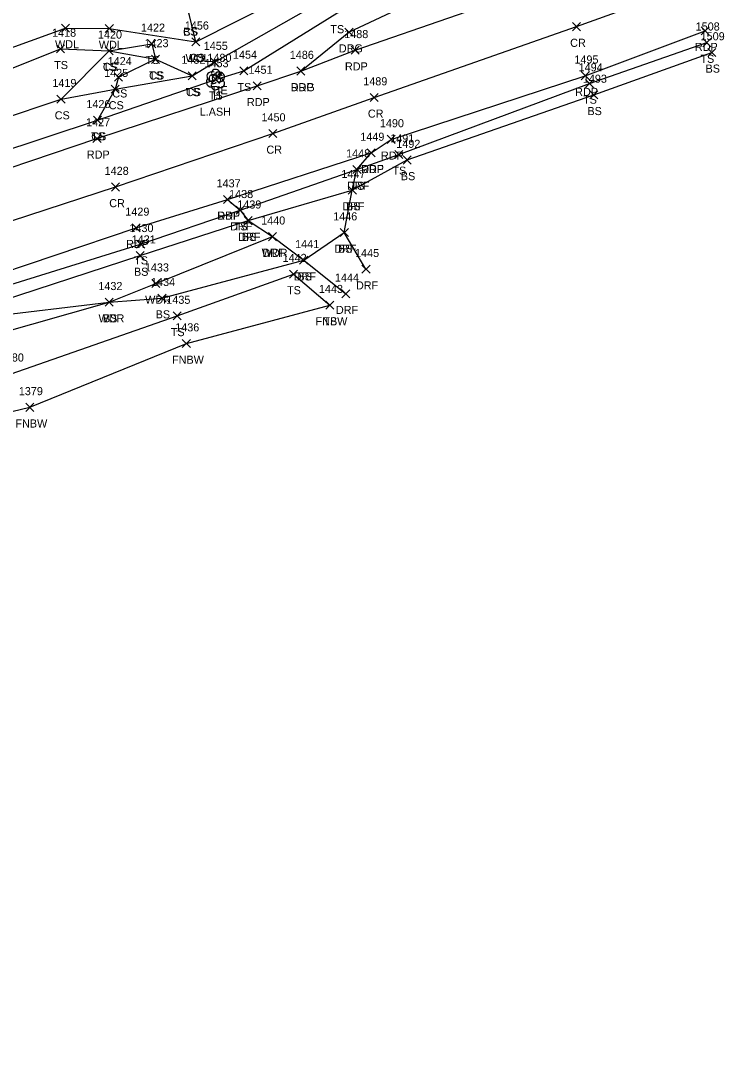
# Model space of a CAD drawing. Extents: x 1443064 to 1445163, y 544063 to 544655.
# Drawn here: x 1443666.1 to 1443840.1, y 544086.5 to 544343.6 of the extents above; entities that cross this region are included whole.
import ezdxf

# ---------------------------------------------------------------- set-up
doc = ezdxf.new("R2010")
doc.units = 0
for name, color, linetype in [('C_A', 7, 'Continuous'), ('C_I', 7, 'Continuous'), ('CBP', 7, 'Continuous'), ('L_A', 7, 'Continuous'), ('L_C', 7, 'Continuous'), ('L_I', 7, 'Continuous'), ('L_TIC', 7, 'Continuous'), ('LAWA', 7, 'Continuous'), ('LELB', 7, 'Continuous'), ('LFNC', 7, 'Continuous'), ('LTD', 7, 'Continuous'), ('P_A', 7, 'Continuous'), ('P_I', 7, 'Continuous'), ('P_TIC', 7, 'Continuous'), ('PET', 7, 'Continuous'), ('PRC', 7, 'Continuous'), ('R_A', 7, 'Continuous'), ('R_I', 7, 'Continuous'), ('R_TIC', 7, 'Continuous'), ('RDF', 7, 'Continuous'), ('RDG', 7, 'Continuous')]:
    doc.layers.add(name, color=color, linetype=linetype)

msp = doc.modelspace()

# ---------------------------------------------------------------- linework, layer by layer
at = {"layer": 'CBP'}
for radius in [0.625, 0.0833]:
    msp.add_circle((1443715.06, 544330.48), radius, dxfattribs=at)
at = {"layer": 'L_TIC'}
for points in [[(1443676.18, 544340.83), (1443678.18, 544342.83)], [(1443678.18, 544340.83), (1443676.18, 544342.83)], [(1443687.03, 544340.71), (1443689.03, 544342.71)], [(1443689.03, 544340.71), (1443687.03, 544342.71)], [(1443674.99, 544335.7), (1443676.99, 544337.7)], [(1443676.99, 544335.7), (1443674.99, 544337.7)], [(1443687, 544335.24), (1443689, 544337.24)], [(1443689, 544335.24), (1443687, 544337.24)], [(1443687, 544335.24), (1443689, 544337.24)], [(1443689, 544335.24), (1443687, 544337.24)], [(1443697.55, 544336.96), (1443699.55, 544338.96)], [(1443699.55, 544336.96), (1443697.55, 544338.96)], [(1443708.45, 544337.47), (1443710.45, 544339.47)], [(1443710.45, 544337.47), (1443708.45, 544339.47)], [(1443708.45, 544337.47), (1443710.45, 544339.47)], [(1443710.45, 544337.47), (1443708.45, 544339.47)], [(1443834.8, 544337.24), (1443836.8, 544339.24)], [(1443836.8, 544337.24), (1443834.8, 544339.24)], [(1443698.43, 544333.12), (1443700.43, 544335.12)], [(1443700.43, 544333.12), (1443698.43, 544335.12)], [(1443698.43, 544333.12), (1443700.43, 544335.12)], [(1443700.43, 544333.12), (1443698.43, 544335.12)], [(1443713.07, 544332.45), (1443715.07, 544334.45)], [(1443715.07, 544332.45), (1443713.07, 544334.45)], [(1443836.04, 544334.82), (1443838.04, 544336.82)], [(1443838.04, 544334.82), (1443836.04, 544336.82)], [(1443720.31, 544330.26), (1443722.31, 544332.26)], [(1443722.31, 544330.26), (1443720.31, 544332.26)], [(1443689.33, 544328.68), (1443691.33, 544330.68)], [(1443691.33, 544328.68), (1443689.33, 544330.68)], [(1443707.55, 544329.01), (1443709.55, 544331.01)], [(1443709.55, 544329.01), (1443707.55, 544331.01)], [(1443707.55, 544329.01), (1443709.55, 544331.01)], [(1443709.55, 544329.01), (1443707.55, 544331.01)], [(1443713.26, 544328.16), (1443715.26, 544330.16)], [(1443715.26, 544328.16), (1443713.26, 544330.16)], [(1443688.45, 544325.75), (1443690.45, 544327.75)], [(1443690.45, 544325.75), (1443688.45, 544327.75)], [(1443688.45, 544325.75), (1443690.45, 544327.75)], [(1443690.45, 544325.75), (1443688.45, 544327.75)], [(1443805.78, 544327.14), (1443807.78, 544329.14)], [(1443807.78, 544327.14), (1443805.78, 544329.14)], [(1443675.09, 544323.26), (1443677.09, 544325.26)], [(1443677.09, 544323.26), (1443675.09, 544325.26)], [(1443675.09, 544323.26), (1443677.09, 544325.26)], [(1443677.09, 544323.26), (1443675.09, 544325.26)], [(1443806.82, 544324.32), (1443808.82, 544326.32)], [(1443808.82, 544324.32), (1443806.82, 544326.32)], [(1443684.12, 544318.06), (1443686.12, 544320.06)], [(1443686.12, 544318.06), (1443684.12, 544320.06)], [(1443684.12, 544318.06), (1443686.12, 544320.06)], [(1443686.12, 544318.06), (1443684.12, 544320.06)], [(1443758.63, 544309.57), (1443760.63, 544311.57)], [(1443760.63, 544309.57), (1443758.63, 544311.57)], [(1443760.69, 544308.21), (1443762.69, 544310.21)], [(1443762.69, 544308.21), (1443760.69, 544310.21)], [(1443748.28, 544305.83), (1443750.28, 544307.83)], [(1443750.28, 544305.83), (1443748.28, 544307.83)], [(1443747.12, 544300.75), (1443749.12, 544302.75)], [(1443749.12, 544300.75), (1443747.12, 544302.75)], [(1443719.36, 544295.79), (1443721.36, 544297.79)], [(1443721.36, 544295.79), (1443719.36, 544297.79)], [(1443721.38, 544293.2), (1443723.38, 544295.2)], [(1443723.38, 544293.2), (1443721.38, 544295.2)], [(1443727.36, 544289.25), (1443729.36, 544291.25)], [(1443729.36, 544289.25), (1443727.36, 544291.25)], [(1443745.14, 544290.27), (1443747.14, 544292.27)], [(1443747.14, 544290.27), (1443745.14, 544292.27)], [(1443694.78, 544287.38), (1443696.78, 544289.38)], [(1443696.78, 544287.38), (1443694.78, 544289.38)], [(1443694.69, 544284.56), (1443696.69, 544286.56)], [(1443696.69, 544284.56), (1443694.69, 544286.56)], [(1443735.1, 544283.41), (1443737.1, 544285.41)], [(1443737.1, 544283.41), (1443735.1, 544285.41)], [(1443732.57, 544279.99), (1443734.57, 544281.99)], [(1443734.57, 544279.99), (1443732.57, 544281.99)], [(1443698.53, 544277.63), (1443700.53, 544279.63)], [(1443700.53, 544277.63), (1443698.53, 544279.63)], [(1443700.05, 544274.03), (1443702.05, 544276.03)], [(1443702.05, 544274.03), (1443700.05, 544276.03)], [(1443687.01, 544273.03), (1443689.01, 544275.03)], [(1443689.01, 544273.03), (1443687.01, 544275.03)], [(1443687.01, 544273.03), (1443689.01, 544275.03)], [(1443689.01, 544273.03), (1443687.01, 544275.03)], [(1443741.56, 544272.31), (1443743.56, 544274.31)], [(1443743.56, 544272.31), (1443741.56, 544274.31)], [(1443741.56, 544272.31), (1443743.56, 544274.31)], [(1443743.56, 544272.31), (1443741.56, 544274.31)], [(1443703.83, 544269.63), (1443705.83, 544271.63)], [(1443705.83, 544269.63), (1443703.83, 544271.63)], [(1443706.08, 544262.81), (1443708.08, 544264.81)], [(1443708.08, 544262.81), (1443706.08, 544264.81)], [(1443667.35, 544247.03), (1443669.35, 544249.03)], [(1443669.35, 544247.03), (1443667.35, 544249.03)]]:
    msp.add_lwpolyline(points, dxfattribs=at)
at = {"layer": 'LAWA'}
for points in [[(1443161.29, 544157.23), (1443186.09, 544163.69), (1443194.34, 544166.63), (1443196.33, 544167.63), (1443201.36, 544168), (1443240.97, 544179.17), (1443262.42, 544188.86), (1443303.08, 544207.19), (1443347.02, 544222.79), (1443391.79, 544240.14), (1443432.68, 544254.71), (1443466.61, 544275.19), (1443493.21, 544282.75), (1443512.25, 544287.37), (1443549.07, 544304.36), (1443598.9, 544317.54), (1443643.36, 544329.59), (1443677.18, 544341.83), (1443688.03, 544341.71), (1443709.45, 544338.47), (1443741.32, 544354.61), (1443794.32, 544372.46), (1443818.98, 544380.86)], [(1443500.75, 544181.56), (1443538.36, 544200.41), (1443545.67, 544211.73), (1443545.24, 544222.13), (1443545.25, 544228.26), (1443572.28, 544239.94), (1443578.87, 544240.7), (1443627.04, 544255.63), (1443659.19, 544265.88), (1443688.01, 544274.03), (1443699.53, 544278.63), (1443728.36, 544290.25)]]:
    msp.add_lwpolyline(points, dxfattribs=at)
at = {"layer": 'LELB'}
for points in [[(1443709.45, 544338.47), (1443707.83, 544344.95), (1443703.92, 544359), (1443695.19, 544383.66), (1443684.28, 544401.01), (1443673.16, 544428.92), (1443681.36, 544433.25), (1443692.26, 544420.67), (1443707.68, 544399.77), (1443719.31, 544385.05), (1443731.94, 544364.15), (1443741.32, 544354.61)], [(1443073.59, 544128.34), (1443116.66, 544141.89), (1443162.8, 544149.75), (1443198.07, 544157.24), (1443242.5, 544173.41), (1443262.84, 544182.05), (1443307.11, 544199.46), (1443348.85, 544214.35), (1443394.74, 544233.02), (1443435.02, 544243.93), (1443473.16, 544259.47), (1443514.32, 544272.16), (1443555.56, 544285.54), (1443605.06, 544302.52), (1443644.56, 544313.72), (1443676.09, 544324.26), (1443689.45, 544326.75), (1443708.55, 544330.01), (1443714.07, 544333.45), (1443742.84, 544349.83), (1443793.92, 544368.99), (1443822.61, 544377.56)], [(1443074.67, 544122.4), (1443120.32, 544131.74), (1443165.11, 544143.77), (1443199.58, 544153.13), (1443245.24, 544167.88), (1443264.59, 544177.57), (1443308.86, 544194.48), (1443350.56, 544209.36), (1443397.32, 544225.82), (1443437.1, 544238.98), (1443476.53, 544253.14), (1443516.75, 544265.8), (1443558.95, 544280.95), (1443607.52, 544296.39), (1443646.45, 544306.32), (1443685.12, 544319.06), (1443714.26, 544329.16), (1443721.31, 544331.26), (1443744.28, 544345.57), (1443795.65, 544366.53), (1443822.61, 544377.56)], [(1443082.68, 544086.51), (1443130.13, 544099.67), (1443144.13, 544104.98), (1443172.72, 544113.76), (1443212.83, 544125.42), (1443253.97, 544138.87), (1443319.39, 544160.76), (1443361, 544176.06), (1443409.52, 544193.8), (1443447.54, 544206.03), (1443485.93, 544218.99), (1443527.17, 544233.73), (1443570.65, 544246.93), (1443621.44, 544264.66), (1443656.15, 544276.08), (1443695.78, 544288.38), (1443720.36, 544296.79), (1443749.28, 544306.83), (1443759.63, 544310.57), (1443806.78, 544328.14), (1443835.8, 544338.24)], [(1443466.61, 544275.19), (1443490.52, 544288.37), (1443512.25, 544287.37), (1443553.95, 544298.49), (1443601.6, 544310.47), (1443642.31, 544323.29), (1443675.99, 544336.7), (1443688, 544336.24), (1443698.55, 544337.96), (1443699.43, 544334.12), (1443708.55, 544330.01)], [(1443319.92, 544153.98), (1443361.38, 544174.3), (1443410.41, 544191.66), (1443447.48, 544203.1), (1443486.62, 544216.08), (1443527.2, 544231.22), (1443571.34, 544244.18), (1443622.82, 544261.27), (1443656.98, 544272.97), (1443695.69, 544285.56), (1443722.38, 544294.2), (1443748.12, 544301.75), (1443761.69, 544309.21), (1443807.82, 544325.32), (1443837.04, 544335.82)], [(1443676.09, 544324.26), (1443688, 544336.24), (1443699.43, 544334.12), (1443690.33, 544329.68), (1443689.45, 544326.75), (1443685.12, 544319.06)], [(1443347.34, 544164.94), (1443362.1, 544171.53), (1443410.79, 544190.32), (1443447.84, 544201.59), (1443487.26, 544214.65), (1443527.73, 544229.42), (1443571.89, 544241.52), (1443623.27, 544260), (1443657.62, 544270.44), (1443688.01, 544274.03), (1443701.05, 544275.03), (1443736.1, 544284.41), (1443746.14, 544291.27)], [(1443551.85, 544201.5), (1443561.2, 544211.49), (1443566.76, 544221.91), (1443582.29, 544226.85), (1443631, 544245.39), (1443663.73, 544256.35), (1443704.83, 544270.63), (1443733.57, 544280.99), (1443742.56, 544273.31)]]:
    msp.add_lwpolyline(points, dxfattribs=at)
at = {"layer": 'LFNC'}
msp.add_lwpolyline([(1443239.88, 544119.45), (1443278.62, 544130.94), (1443320.57, 544148.06), (1443338.13, 544157.08), (1443351.22, 544161.82), (1443363.5, 544166.21), (1443412.24, 544182.91), (1443449.91, 544194.79), (1443489.63, 544207.22), (1443534.54, 544218.89), (1443545.24, 544222.13), (1443555.28, 544222.99), (1443566.76, 544221.91), (1443584.49, 544223.6), (1443632.95, 544239.56), (1443668.35, 544248.03), (1443707.08, 544263.81), (1443742.56, 544273.31)], dxfattribs=at)
at = {"layer": 'LTD'}
msp.add_line((1443714.26, 544329.16), (1443714.26, 544329.16), dxfattribs=at)
msp.add_line((1443714.26, 544329.16), (1443714.26, 544329.16), dxfattribs=at)
msp.add_arc((1443714.31, 544330.59), 1.05, 335.5272, 180.9563, dxfattribs=at)
for centre, major_axis, ratio, start_param, end_param in [((1443713.18, 544328.45), (0.58, -1.04), 0.959034, 3.141593, 6.283185), ((1443713.47, 544329.82), (1.21, -0.51), 0.895232, 1.570796, 4.712389), ((1443714.05, 544329.62), (-0.208, -0.792), 0.645439, 3.141593, 6.283185), ((1443714.76, 544328.99), (-0.5, 0.667), 0.989748, 3.141593, 6.283185), ((1443715.3, 544329.74), (-1.14, -0.48), 0.949671, 1.570796, 4.712389), ((1443714.26, 544327.66), (0.26, 1.06), 0.942809, 1.570796, 4.712389), ((1443713.8, 544328.41), (-0.625, -0.083), 0.423636, 0, 3.141593), ((1443715.26, 544328.32), (-1.09, 0.79), 0.841452, 1.570796, 4.712389)]:
    msp.add_ellipse(centre, major_axis=major_axis, ratio=ratio, start_param=start_param, end_param=end_param, dxfattribs=at)
at = {"layer": 'P_TIC'}
for points in [[(1443802.56, 544341.2), (1443804.56, 544343.2)], [(1443804.56, 544341.2), (1443802.56, 544343.2)], [(1443834.35, 544340.18), (1443836.35, 544342.18)], [(1443836.35, 544340.18), (1443834.35, 544342.18)], [(1443747.81, 544335.36), (1443749.81, 544337.36)], [(1443749.81, 544335.36), (1443747.81, 544337.36)], [(1443734.41, 544330.22), (1443736.41, 544332.22)], [(1443736.41, 544330.22), (1443734.41, 544332.22)], [(1443804.74, 544329.07), (1443806.74, 544331.07)], [(1443806.74, 544329.07), (1443804.74, 544331.07)], [(1443723.57, 544326.54), (1443725.57, 544328.54)], [(1443725.57, 544326.54), (1443723.57, 544328.54)], [(1443752.53, 544323.68), (1443754.53, 544325.68)], [(1443754.53, 544323.68), (1443752.53, 544325.68)], [(1443727.44, 544314.77), (1443729.44, 544316.77)], [(1443729.44, 544314.77), (1443727.44, 544316.77)], [(1443683.98, 544313.55), (1443685.98, 544315.55)], [(1443685.98, 544313.55), (1443683.98, 544315.55)], [(1443756.72, 544313.31), (1443758.72, 544315.31)], [(1443758.72, 544313.31), (1443756.72, 544315.31)], [(1443751.8, 544309.97), (1443753.8, 544311.97)], [(1443753.8, 544309.97), (1443751.8, 544311.97)], [(1443688.58, 544301.53), (1443690.58, 544303.53)], [(1443690.58, 544301.53), (1443688.58, 544303.53)], [(1443716.24, 544298.44), (1443718.24, 544300.44)], [(1443718.24, 544298.44), (1443716.24, 544300.44)], [(1443693.69, 544291.43), (1443695.69, 544293.43)], [(1443695.69, 544291.43), (1443693.69, 544293.43)]]:
    msp.add_lwpolyline(points, dxfattribs=at)
at = {"layer": 'PET'}
for points in [[(1443075.39, 544117.71), (1443121.41, 544129.24), (1443165.99, 544140.07), (1443200.71, 544149.88), (1443246.42, 544165.39), (1443265.96, 544172.48), (1443311.2, 544187.88), (1443352.92, 544202.76), (1443399.28, 544220.13), (1443438.78, 544233.67), (1443478.75, 544247.35), (1443518.41, 544260.6), (1443561.23, 544274.05), (1443611.7, 544290.5), (1443646.84, 544301.68), (1443684.98, 544314.55), (1443724.57, 544327.54), (1443735.41, 544331.22), (1443748.81, 544336.36), (1443799.43, 544353.96), (1443827.31, 544364.14)], [(1443081.93, 544089.54), (1443128.67, 544104.01), (1443173.03, 544117.15), (1443209.23, 544128.71), (1443253.49, 544142.88), (1443273.3, 544149.07), (1443318.27, 544165.2), (1443359.78, 544179.84), (1443408.54, 544196.96), (1443445.92, 544210.12), (1443484.92, 544223.61), (1443525.67, 544237.02), (1443568.63, 544251.04), (1443620.57, 544267.93), (1443654.52, 544278.93), (1443694.69, 544292.43), (1443717.24, 544299.44), (1443752.8, 544310.97), (1443757.72, 544314.31), (1443805.74, 544330.07), (1443835.35, 544341.18)]]:
    msp.add_lwpolyline(points, dxfattribs=at)
at = {"layer": 'PRC'}
msp.add_lwpolyline([(1443078.47, 544103.68), (1443125.02, 544115.93), (1443169.41, 544128.22), (1443204.47, 544139.4), (1443250.36, 544154.3), (1443269.99, 544160.83), (1443315.13, 544176.71), (1443356.58, 544191.19), (1443403.59, 544208.05), (1443442.67, 544222.02), (1443482.15, 544235.41), (1443522.16, 544248.37), (1443565.47, 544262.64), (1443616.51, 544279.34), (1443650.9, 544289.93), (1443689.58, 544302.53), (1443728.44, 544315.77), (1443753.53, 544324.68), (1443803.56, 544342.2), (1443830.96, 544352.16)], dxfattribs=at)
at = {"layer": 'R_TIC'}
for points in [[(1443746.3, 544339.82), (1443748.3, 544341.82)], [(1443748.3, 544339.82), (1443746.3, 544341.82)], [(1443734.41, 544330.22), (1443736.41, 544332.22)], [(1443736.41, 544330.22), (1443734.41, 544332.22)], [(1443751.8, 544309.97), (1443753.8, 544311.97)], [(1443753.8, 544309.97), (1443751.8, 544311.97)], [(1443748.28, 544305.83), (1443750.28, 544307.83)], [(1443750.28, 544305.83), (1443748.28, 544307.83)], [(1443747.12, 544300.75), (1443749.12, 544302.75)], [(1443749.12, 544300.75), (1443747.12, 544302.75)], [(1443716.24, 544298.44), (1443718.24, 544300.44)], [(1443718.24, 544298.44), (1443716.24, 544300.44)], [(1443719.36, 544295.79), (1443721.36, 544297.79)], [(1443721.36, 544295.79), (1443719.36, 544297.79)], [(1443721.38, 544293.2), (1443723.38, 544295.2)], [(1443723.38, 544293.2), (1443721.38, 544295.2)], [(1443727.36, 544289.25), (1443729.36, 544291.25)], [(1443729.36, 544289.25), (1443727.36, 544291.25)], [(1443745.14, 544290.27), (1443747.14, 544292.27)], [(1443747.14, 544290.27), (1443745.14, 544292.27)], [(1443735.1, 544283.41), (1443737.1, 544285.41)], [(1443737.1, 544283.41), (1443735.1, 544285.41)], [(1443750.5, 544281.2), (1443752.5, 544283.2)], [(1443752.5, 544281.2), (1443750.5, 544283.2)], [(1443745.53, 544275.13), (1443747.53, 544277.13)], [(1443747.53, 544275.13), (1443745.53, 544277.13)]]:
    msp.add_lwpolyline(points, dxfattribs=at)
at = {"layer": 'RDF'}
for points in [[(1443751.5, 544282.2), (1443746.14, 544291.27), (1443748.12, 544301.75), (1443749.28, 544306.83), (1443752.8, 544310.97)], [(1443717.24, 544299.44), (1443720.36, 544296.79), (1443722.38, 544294.2), (1443728.36, 544290.25), (1443736.1, 544284.41), (1443746.53, 544276.13)]]:
    msp.add_lwpolyline(points, dxfattribs=at)
at = {"layer": 'RDG'}
msp.add_lwpolyline([(1443735.41, 544331.22), (1443747.3, 544340.82), (1443796.71, 544364.11), (1443823.11, 544373.78)], dxfattribs=at)

# ---------------------------------------------------------------- texts
at = {"layer": 'C_A'}
msp.add_text('TIE', height=2, dxfattribs=at).set_placement((1443713.14, 544325.48))
at = {"layer": 'C_I'}
msp.add_text('1480', height=2, dxfattribs=at).set_placement((1443712.29, 544333.48))
at = {"layer": 'L_A'}
for s, p in [('TS', (1443742.69, 544340.57)), ('CS', (1443706.27, 544339.95)), ('BS', (1443706.27, 544339.95)), ('WDL', (1443674.6, 544336.83)), ('WDL', (1443685.44, 544336.71)), ('TS', (1443696.96, 544332.96)), ('WDL', (1443706.87, 544333.47)), ('CS', (1443707.89, 544333.47)), ('TS', (1443834.21, 544333.24)), ('TS', (1443674.4, 544331.7)), ('TS', (1443686.41, 544331.24)), ('CS', (1443686.44, 544331.24)), ('BS', (1443835.48, 544330.82)), ('TS', (1443697.84, 544329.12)), ('CS', (1443697.87, 544329.12)), ('CS', (1443712.52, 544328.45)), ('TS', (1443706.96, 544325.01)), ('CS', (1443706.99, 544325.01)), ('TS', (1443719.72, 544326.26)), ('CS', (1443688.77, 544324.68)), ('TS', (1443712.67, 544324.16)), ('H', (1443713.69, 544324.16)), ('TS', (1443805.19, 544323.14)), ('CS', (1443687.89, 544321.75)), ('CS', (1443687.89, 544321.75)), ('BS', (1443806.26, 544320.32)), ('CS', (1443674.53, 544319.26)), ('CS', (1443674.53, 544319.26)), ('TS', (1443683.53, 544314.06)), ('CS', (1443683.56, 544314.06)), ('TS', (1443758.04, 544305.57)), ('BS', (1443760.13, 544304.21)), ('TS', (1443747.69, 544301.83)), ('BS', (1443746.56, 544296.75)), ('TS', (1443718.77, 544291.79)), ('BS', (1443720.82, 544289.2)), ('BS', (1443744.58, 544286.27)), ('WDR', (1443725.72, 544285.25)), ('TS', (1443694.19, 544283.38)), ('BS', (1443694.13, 544280.56)), ('BS', (1443734.54, 544279.41)), ('TS', (1443731.98, 544275.99)), ('WDR', (1443696.89, 544273.63)), ('WDR', (1443685.37, 544269.03)), ('BS', (1443686.45, 544269.03)), ('BS', (1443699.49, 544270.03)), ('FNBW', (1443739.03, 544268.31)), ('TS', (1443740.97, 544268.31)), ('TS', (1443703.24, 544265.63)), ('FNBW', (1443703.55, 544258.81)), ('FNBW', (1443664.82, 544243.03))]:
    msp.add_text(s, height=2, dxfattribs=at).set_placement(p)
at = {"layer": 'L_C'}
msp.add_text('L.ASH', height=2, dxfattribs=at).set_placement((1443710.39, 544320.16))
at = {"layer": 'L_I'}
for s, p in [('1422', (1443695.86, 544340.96)), ('1456', (1443706.7, 544341.47)), ('1456', (1443706.7, 544341.47)), ('1508', (1443833.03, 544341.24)), ('1418', (1443673.87, 544339.7)), ('1420', (1443685.22, 544339.24)), ('1420', (1443685.22, 544339.24)), ('1509', (1443834.26, 544338.82)), ('1423', (1443696.73, 544337.12)), ('1423', (1443696.73, 544337.12)), ('1455', (1443711.38, 544336.45)), ('1424', (1443687.63, 544332.68)), ('1452', (1443705.86, 544333.01)), ('1452', (1443705.86, 544333.01)), ('1454', (1443718.61, 544334.26)), ('1453', (1443711.57, 544332.16)), ('1453', (1443711.57, 544332.16)), ('1494', (1443804.09, 544331.14)), ('1425', (1443686.75, 544329.75)), ('1425', (1443686.75, 544329.75)), ('1493', (1443805.13, 544328.32)), ('1419', (1443673.95, 544327.26)), ('1419', (1443673.95, 544327.26)), ('1426', (1443682.37, 544322.06)), ('1426', (1443682.37, 544322.06)), ('1491', (1443757.5, 544313.57)), ('1492', (1443759, 544312.21)), ('1448', (1443746.59, 544309.83)), ('1447', (1443745.43, 544304.75)), ('1438', (1443717.66, 544299.79)), ('1439', (1443719.68, 544297.2)), ('1446', (1443743.39, 544294.27)), ('1430', (1443693, 544291.38)), ('1440', (1443725.58, 544293.25)), ('1431', (1443693.56, 544288.56)), ('1441', (1443733.98, 544287.41)), ('1442', (1443730.88, 544283.99)), ('1433', (1443696.83, 544281.63)), ('1432', (1443685.32, 544277.03)), ('1432', (1443685.32, 544277.03)), ('1434', (1443698.35, 544278.03)), ('1443', (1443739.86, 544276.31)), ('1443', (1443739.86, 544276.31)), ('1435', (1443702.13, 544273.63)), ('1436', (1443704.33, 544266.81)), ('1380', (1443660.95, 544259.35)), ('1379', (1443665.65, 544251.03))]:
    msp.add_text(s, height=2, dxfattribs=at).set_placement(p)
at = {"layer": 'P_A'}
for s, p in [('CR', (1443801.99, 544337.2)), ('RDP', (1443832.84, 544336.18)), ('RDP', (1443746.3, 544331.36)), ('RDP', (1443732.9, 544326.22)), ('RDP', (1443803.23, 544325.07)), ('RDP', (1443722.06, 544322.54)), ('CR', (1443751.97, 544319.68)), ('RDP', (1443682.47, 544309.55)), ('CR', (1443726.88, 544310.77)), ('RDP', (1443755.2, 544309.31)), ('RDP', (1443750.29, 544305.97)), ('CR', (1443688.01, 544297.53)), ('RDP', (1443714.73, 544294.44)), ('RDP', (1443692.18, 544287.43))]:
    msp.add_text(s, height=2, dxfattribs=at).set_placement(p)
at = {"layer": 'P_I'}
for s, p in [('1488', (1443746.12, 544339.36)), ('1486', (1443732.66, 544334.22)), ('1495', (1443803.04, 544333.07)), ('1451', (1443722.44, 544330.54)), ('1489', (1443750.83, 544327.68)), ('1427', (1443682.29, 544317.55)), ('1450', (1443725.66, 544318.77)), ('1490', (1443754.94, 544317.31)), ('1449', (1443750.1, 544313.97)), ('1428', (1443686.88, 544305.53)), ('1437', (1443714.55, 544302.44)), ('1429', (1443691.99, 544295.43))]:
    msp.add_text(s, height=2, dxfattribs=at).set_placement(p)
at = {"layer": 'R_A'}
for s, p in [('DRG', (1443744.79, 544335.82)), ('DRG', (1443732.9, 544326.22)), ('DRF', (1443750.33, 544305.97)), ('DRF', (1443746.82, 544301.83)), ('DRF', (1443745.65, 544296.75)), ('DRF', (1443714.77, 544294.44)), ('DRF', (1443717.89, 544291.79)), ('DRF', (1443719.91, 544289.2)), ('DRF', (1443743.67, 544286.27)), ('DRF', (1443725.89, 544285.25)), ('DRF', (1443733.64, 544279.41)), ('DRF', (1443749.03, 544277.2)), ('DRF', (1443744.07, 544271.13))]:
    msp.add_text(s, height=2, dxfattribs=at).set_placement(p)
at = {"layer": 'R_I'}
for s, p in [('1486', (1443732.66, 544334.22)), ('1449', (1443750.1, 544313.97)), ('1448', (1443746.59, 544309.83)), ('1447', (1443745.43, 544304.75)), ('1437', (1443714.55, 544302.44)), ('1438', (1443717.66, 544299.79)), ('1439', (1443719.68, 544297.2)), ('1446', (1443743.39, 544294.27)), ('1440', (1443725.58, 544293.25)), ('1441', (1443733.98, 544287.41)), ('1445', (1443748.8, 544285.2)), ('1444', (1443743.84, 544279.13))]:
    msp.add_text(s, height=2, dxfattribs=at).set_placement(p)

doc.saveas('drawing.dxf')
